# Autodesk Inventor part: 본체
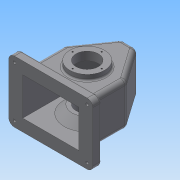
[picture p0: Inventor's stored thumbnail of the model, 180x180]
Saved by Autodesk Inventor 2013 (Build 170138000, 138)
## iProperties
Created: 2016-12
Part Number: 본체
Material: Generic
Document SubType Name: Modeling
Designer: Administrator
Density: 1 g/cm^3
Author: Administrator
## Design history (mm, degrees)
sketch "스케치1"
  geometry: L1 (0, 0)-(0, 80); L2 (0, 80)-(42.012, 140); L3 (0, 0)-(110, 0); L4 (110, 0)-(110, 80); L5 (110, 80)-(67.988, 140); L6 (67.988, 140)-(42.012, 140)
  constraints: 12 end point, 2 perpendicular, 1 equal length, 1 vertical
  dimensions: "d0" = 110 distance of L1.start L3.end; "d1" = 80 distance of L1.start L1.end; "d2" = 35 deg angle of L1 L2; "d3" = 80 distance of L3.end L4.end; "d4" = 140 distance between parallel lines of L3 L6; "d5" = 35 deg angle of L4 L5
extrude "돌출1" new body sketch "스케치1" distance "d6" = 77; taper "d7" = 0 deg
fillet "모깎기1" dims "d8" = 10
feature "쉘1" dims "d9" = 5
node "작업 평면1"
sketch "스케치2"
  geometry: L1 (-132.868, -72)-(-79.715, -72) reference; L2 (-76.847, -72)-(-79.715, -72) reference; L3 (-76.847, -5)-(-76.847, -72) reference; L4 (-76.847, -72)-(0, -72) reference; L5 (0, -5)-(0, -72) reference; L6 (0, -5)-(-76.847, -5) reference; L7 (-135.736, -77)-(-82.583, -77) reference; L8 (-76.847, -77)-(-82.583, -77) reference; L9 (-76.847, -77)-(0, -77) reference; L10 (-106, -72)-(-92, -58); L11 (-92, -58)-(-85, -58); L12 (-85, -58)-(-85, -72); L13 (-65, -72)-(-65, -5)
  constraints: 8 end point, 4 point on line, 2 perpendicular, 1 parallel
  dimensions: "d10" = 65 distance between parallel lines of L5 L13; "d11" = 54 diameter of L10.end L13; "d12" = 40 diameter of L12 L13; "d13" = 45 deg angle of L11 L10; "d14" = 14 distance of L11.end L12.end
revolve "회전1" sketch "스케치2" stored, may be unused: angle "d15" = 90 deg
sketch "스케치3"
  geometry: L1 (-110, 76.847)-(-110, 0) reference; L2 (-110, 0)-(0, 0) reference; C1 r 20 at (-55, 65); C2 r 37.5 at (-55, 65)
  constraints: 2 centre point, 1 coincident
  dimensions: "d16" = 65 distance from line of C1.centre L2; "d17" = 40 diameter of C1; "d18" = 75 diameter of C2; "d19" = 55 distance from line of C1.centre L1
extrude "돌출2" join sketch "스케치3" distance "d20" = 5; taper "d21" = 0 deg
sketch "스케치4"
  geometry: C1 r 20 at (0, 0) reference; C2 r 20 at (0, 0); 1 further point
  constraints: 1 centre point, 1 coincident
  dimensions: "d22" = 40 diameter of C2
extrude "돌출3" cut sketch "스케치4" stored distance "d24" = 5; taper "d25" = 0 deg
sketch "스케치5"
  geometry: C1 r 20 at (55, 65) reference; C2 r 31 at (55, 65); C3 r 20 at (55, 65)
  constraints: 2 centre point, 2 coincident, 1 concentric
  dimensions: "d26" = 62 diameter of C2
extrude "돌출4" join sketch "스케치5" distance "d28" = 10; taper "d29" = 0 deg
node "작업 평면2"
sketch "스케치8"
  geometry: L1 (5, 5)-(5, 72) reference; L2 (110, 0)-(0, 0) reference; L3 (110, 0)-(110, 77) reference; L4 (0, 77)-(110, 77) reference; L5 (0, 0)-(0, 77) reference; L6 (-20, 93.5)-(130, 93.5); L7 (130, 93.5)-(130, -16.5); L8 (130, -16.5)-(-20, -16.5); L9 (-20, -16.5)-(-20, 93.5); 2 further points
  constraints: 8 end point, 2 midpoint, 2 parallel, 1 horizontal, 1 perpendicular
  dimensions: "d40" = 110 distance of L8.end L6.start; "d42" = 150 distance of L6.start L6.end; "d43" = 55 distance from line of point (5, 38.5) L6; "d44" = 75 horizontal distance of L6.start point (55, 77)
extrude "돌출6" join sketch "스케치8" distance "d45" = 15; taper "d46" = 0 deg
fillet "모깎기2" dims "d47" = 8
fillet "모깎기3" dims "d48" = 3
fillet "모깎기4" dims "d49" = 10
fillet "모깎기5" dims "d50" = 3
sketch "스케치9"
  geometry: C1 r 2.5 at (-10, 6.5); C2 r 2.5 at (120, 6.5); C3 r 2.5 at (120, -83.5); C4 r 2.5 at (-10, -83.5); A1 r 7 centre (120, 6.5) between (127, 6.5) and (120, 13.5) reference; A2 r 7 centre (-10, 6.5) between (-10, 13.5) and (-17, 6.5) reference; A3 r 7 centre (-10, -83.5) between (-17, -83.5) and (-10, -90.5) reference; A4 r 7 centre (120, -83.5) between (120, -90.5) and (127, -83.5) reference; 1 further point
  constraints: 4 centre point, 4 coincident
  dimensions: "d51" = 5 diameter of C1; "d53" = 5 diameter of C2; "d54" = 5 diameter of C3; "d55" = 5 diameter of C4
extrude "돌출7" cut sketch "스케치9" stored distance "d56" = 15; taper "d57" = 0 deg
sketch "스케치10"
  geometry: C1 r 2.5 at (120, -83.5) reference; C2 r 2.5 at (-10, 6.5) reference; C3 r 2.5 at (120, 6.5) reference; C4 r 2.5 at (-10, -83.5) reference; C5 r 6 at (-10, 6.5); C6 r 6 at (120, 6.5); C7 r 6 at (120, -83.5); C8 r 6 at (-10, -83.5); A1 r 7 centre (120, 6.5) between (127, 6.5) and (120, 13.5) reference; A2 r 7 centre (-10, 6.5) between (-10, 13.5) and (-17, 6.5) reference; A3 r 7 centre (-10, -83.5) between (-17, -83.5) and (-10, -90.5) reference; A4 r 7 centre (120, -83.5) between (120, -90.5) and (127, -83.5) reference; 1 further point
  constraints: 4 centre point, 4 coincident
  dimensions: "d58" = 12 diameter of C5; "d60" = 12 diameter of C6; "d61" = 12 diameter of C7; "d62" = 12 diameter of C8
extrude "돌출8" cut sketch "스케치10" distance "d63" = 5; taper "d64" = 0 deg
sketch "스케치11" dims "d65" = 52
  geometry: C1 r 20 at (0, 0) reference; C2 r 31 at (0, 0) reference; 6 further points
  constraints: 2 vertical alignment, 1 coincident, 7 other
  dimensions: "d69" = 360 deg dimension on point (0, 0) point (0, 26) (derived)
hole "구멍1" sketch "스케치11" at (0, 26), (-26, 0), (0, -26), (26, 0) diameter "d71" = 2.459; stored, may be unused: countersink angle "d75" = 90 deg, drill point angle "d77" = 118 deg; dims "d72" = 6, "d73" = 4, "d74" = 2, "d76" = 8
node "작업 평면3"
node "작업 평면4"
node "작업 평면5"
sketch "스케치12" dims "d78" = 52
  geometry: C1 r 20 at (0, 0) reference; C2 r 37.5 at (0, 0) reference; 6 further points
  constraints: 2 vertical alignment, 1 coincident, 7 other
  dimensions: "d82" = 360 deg dimension on point (0, 0) point (0, 26) (derived)
hole "구멍2" sketch "스케치12" at (0, 26), (-26, 0), (0, -26), (26, 0) diameter "d84" = 2.459; stored, may be unused: countersink angle "d88" = 90 deg, drill point angle "d90" = 118 deg; dims "d85" = 6, "d86" = 4, "d87" = 2, "d89" = 8
sketch "스케치13"
  geometry: L1 (-0.044, -31.847)-(61.044, -31.847); L2 (30.5, -38.846)-(30.5, -24.848); L3 (-8, 0)-(-8, -58.847) reference; L4 (-14.5, -76.847)-(75.5, -76.847) reference; L5 (6.122, -28.706)-(55.897, -28.706); L6 (55.897, -28.706)-(55.897, -35.91); L7 (55.897, -35.91)-(6.122, -35.91); L8 (6.122, -35.91)-(6.122, -28.706); 1 further point
  constraints: 4 end point, 2 other
  dimensions: "d91" = 38.5 distance from line of L2.end L3; "d92" = 45 distance from line of L4 L1.end
feature "엠보싱1" sketch "스케치13" dims "d1" = 80, "d93" = 0.5, "d94" = 0
node "솔리드1"
mirror "대칭1"
node "투영된 루프1"
other parameters: "d33" = 65
